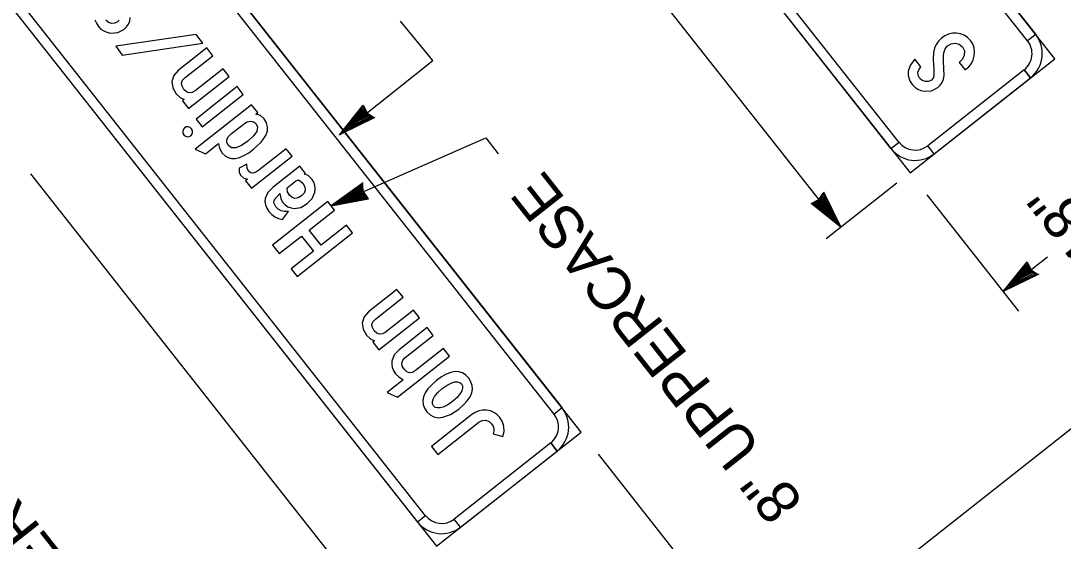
# Model space of a CAD drawing. Extents: x 672438 to 673980, y 1673259 to 1674850.
# Drawn here: x 673725.7 to 673827.5, y 1673361.1 to 1673411.9 of the extents above; entities that cross this region are included whole.
import ezdxf

# ---------------------------------------------------------------- set-up
doc = ezdxf.new("R2010")
doc.units = 0
doc.layers.add('C-ANNO-SYMB', color=7, linetype='Continuous')
doc.layers.add('Level 1', color=7, linetype='Continuous')

msp = doc.modelspace()

# ---------------------------------------------------------------- linework, layer by layer
at = {"layer": 'C-ANNO-SYMB'}
for p, q in [((673826.68, 1673408.21), (673748.67, 1673507.16)), ((673750.53, 1673504.8), (673824.82, 1673410.57)), ((673824.03, 1673409.95), (673749.74, 1673504.19)), ((673734.53, 1673496.02), (673812.54, 1673397.07)), ((673736.39, 1673493.66), (673810.68, 1673399.42)), ((673811.47, 1673400.04), (673737.18, 1673494.28)), ((673780.41, 1673371.74), (673702.41, 1673470.69)), ((673704.26, 1673468.33), (673778.56, 1673374.1)), ((673777.77, 1673373.48), (673703.48, 1673467.71)), ((673688.27, 1673459.54), (673766.28, 1673360.6)), ((673765.2, 1673363.57), (673690.91, 1673457.81)), ((673690.13, 1673457.19), (673764.42, 1673362.95)), ((673824.82, 1673410.57), (673824.03, 1673409.95)), ((673824.82, 1673410.57), (673824.03, 1673409.95)), ((673824.03, 1673409.95), (673824.03, 1673409.95)), ((673824.03, 1673409.95), (673824.03, 1673409.95)), ((673812.54, 1673397.07), (673826.68, 1673408.21)), ((673826.68, 1673408.21), (673826.68, 1673408.21)), ((673826.68, 1673408.21), (673826.68, 1673408.21)), ((673823.7, 1673407.14), (673814.28, 1673399.71)), ((673823.7, 1673407.14), (673824.32, 1673406.35)), ((673824.32, 1673406.35), (673823.7, 1673407.14)), ((673823.7, 1673407.14), (673824.32, 1673406.35)), ((673814.9, 1673398.92), (673824.32, 1673406.35)), ((673811.47, 1673400.04), (673810.68, 1673399.42)), ((673811.47, 1673400.04), (673810.68, 1673399.42)), ((673814.9, 1673398.92), (673814.28, 1673399.71)), ((673814.28, 1673399.71), (673814.28, 1673399.71)), ((673814.28, 1673399.71), (673814.28, 1673399.71)), ((673814.9, 1673398.92), (673814.28, 1673399.71)), ((673778.56, 1673374.1), (673777.77, 1673373.48)), ((673778.56, 1673374.1), (673777.77, 1673373.48)), ((673777.77, 1673373.48), (673777.77, 1673373.48)), ((673777.77, 1673373.48), (673777.77, 1673373.48)), ((673766.28, 1673360.6), (673780.41, 1673371.74)), ((673780.41, 1673371.74), (673780.41, 1673371.74)), ((673780.41, 1673371.74), (673780.41, 1673371.74)), ((673777.44, 1673370.67), (673768.01, 1673363.24)), ((673777.44, 1673370.67), (673778.06, 1673369.88)), ((673778.06, 1673369.88), (673777.44, 1673370.67)), ((673777.44, 1673370.67), (673778.06, 1673369.88)), ((673768.63, 1673362.45), (673778.06, 1673369.88)), ((673765.2, 1673363.57), (673764.42, 1673362.95)), ((673765.2, 1673363.57), (673764.42, 1673362.95)), ((673768.63, 1673362.45), (673768.01, 1673363.24)), ((673768.01, 1673363.24), (673768.01, 1673363.24)), ((673768.01, 1673363.24), (673768.01, 1673363.24)), ((673768.63, 1673362.45), (673768.01, 1673363.24))]:
    msp.add_line(p, q, dxfattribs=at)
for points in [[(673732.91, 1673412), (673733.05, 1673411.68), (673733.26, 1673411.36), (673733.5, 1673411.11), (673733.78, 1673410.92), (673734.09, 1673410.79), (673734.44, 1673410.72), (673735.14, 1673410.77), (673735.74, 1673411.08), (673735.99, 1673411.32), (673736.18, 1673411.59), (673736.31, 1673411.9), (673736.37, 1673412.25)], [(673735.29, 1673411.99), (673735.13, 1673411.81), (673734.85, 1673411.67), (673734.53, 1673411.66), (673734.23, 1673411.76), (673733.99, 1673411.97)], [(673748.82, 1673402.94), (673748.21, 1673403.71), (673742.71, 1673399.37), (673743.73, 1673398.93), (673744.98, 1673399.92), (673745.07, 1673399.46), (673745.35, 1673398.99), (673745.62, 1673398.72), (673745.92, 1673398.55), (673746.25, 1673398.46), (673746.62, 1673398.47), (673747.03, 1673398.56), (673747.47, 1673398.75), (673747.94, 1673399.03), (673748.45, 1673399.4), (673749.15, 1673400.05), (673749.6, 1673400.71), (673749.76, 1673401.15), (673749.78, 1673401.57), (673749.68, 1673401.96), (673749.45, 1673402.34), (673749.08, 1673402.65), (673748.63, 1673402.79), (673748.82, 1673402.94)], [(673747.52, 1673401.89), (673747.8, 1673402.05), (673748.1, 1673402.11), (673748.42, 1673402.05), (673748.66, 1673401.85), (673748.81, 1673401.51), (673748.72, 1673401.11), (673748.4, 1673400.67), (673747.85, 1673400.17), (673747.22, 1673399.74), (673746.69, 1673399.51), (673746.27, 1673399.51), (673745.96, 1673399.72), (673745.81, 1673400.01), (673745.81, 1673400.31), (673745.96, 1673400.6), (673746.27, 1673400.9), (673747.52, 1673401.89)], [(673753.49, 1673397.01), (673752.93, 1673397.72), (673750.31, 1673395.65), (673749.8, 1673395.13), (673749.54, 1673394.57), (673749.51, 1673394.25), (673749.56, 1673393.93), (673749.69, 1673393.61), (673749.9, 1673393.3), (673750.18, 1673393), (673750.49, 1673392.77), (673750.85, 1673392.61), (673751.23, 1673392.51), (673751.81, 1673393.28), (673751.43, 1673393.28), (673751.1, 1673393.36), (673750.81, 1673393.52), (673750.58, 1673393.74), (673750.39, 1673394.13), (673750.44, 1673394.46), (673750.98, 1673395.03), (673751.06, 1673394.56), (673751.25, 1673394.19), (673751.5, 1673393.93), (673751.77, 1673393.75), (673752.07, 1673393.63), (673752.39, 1673393.58), (673753.03, 1673393.69), (673753.64, 1673394.05), (673754.12, 1673394.56), (673754.38, 1673395.17), (673754.43, 1673395.52), (673754.4, 1673395.84), (673754.3, 1673396.14), (673754.12, 1673396.42), (673753.74, 1673396.79), (673753.38, 1673396.92), (673753.49, 1673397.01)], [(673751.69, 1673395.59), (673752.52, 1673396.25), (673752.69, 1673396.33), (673752.86, 1673396.33), (673753.04, 1673396.23), (673753.22, 1673396.04), (673753.41, 1673395.71), (673753.44, 1673395.38), (673753.34, 1673395.08), (673753.09, 1673394.81), (673752.76, 1673394.61), (673752.45, 1673394.55), (673752.17, 1673394.64), (673751.91, 1673394.88), (673751.74, 1673395.2), (673751.69, 1673395.59)], [(673766.27, 1673376.76), (673765.81, 1673376.36), (673765.44, 1673375.96), (673765.18, 1673375.57), (673765.01, 1673375.19), (673764.94, 1673374.81), (673764.97, 1673374.44), (673765.1, 1673374.08), (673765.33, 1673373.72), (673765.65, 1673373.41), (673766.02, 1673373.21), (673766.43, 1673373.14), (673766.89, 1673373.18), (673767.65, 1673373.46), (673768.45, 1673373.99), (673768.92, 1673374.39), (673769.29, 1673374.79), (673769.56, 1673375.18), (673769.73, 1673375.56), (673769.81, 1673375.93), (673769.78, 1673376.3), (673769.65, 1673376.66), (673769.43, 1673377.01), (673769.14, 1673377.3), (673768.82, 1673377.51), (673768.47, 1673377.62), (673768.09, 1673377.64), (673767.68, 1673377.56), (673767.24, 1673377.39), (673766.77, 1673377.12), (673766.27, 1673376.76)], [(673766.84, 1673375.98), (673767.32, 1673376.32), (673767.77, 1673376.55), (673768.07, 1673376.64), (673768.33, 1673376.65), (673768.55, 1673376.58), (673768.71, 1673376.44), (673768.81, 1673376.24), (673768.83, 1673376.02), (673768.76, 1673375.77), (673768.6, 1673375.5), (673768.29, 1673375.11), (673767.85, 1673374.73), (673767.38, 1673374.4), (673766.93, 1673374.18), (673766.63, 1673374.1), (673766.38, 1673374.09), (673766.16, 1673374.15), (673766, 1673374.3), (673765.9, 1673374.49), (673765.88, 1673374.71), (673765.95, 1673374.95), (673766.1, 1673375.22), (673766.41, 1673375.6), (673766.84, 1673375.98)]]:
    msp.add_lwpolyline(points, dxfattribs=at)
for points in [[(673743.46, 1673409.73), (673742.8, 1673410.57), (673734.94, 1673409.45), (673735.56, 1673408.57)], [(673817.92, 1673407.11), (673817.97, 1673407.15), (673818.28, 1673407.43), (673818.53, 1673407.74), (673818.7, 1673408.1), (673818.81, 1673408.48), (673818.85, 1673408.89), (673818.8, 1673409.28), (673818.67, 1673409.65), (673818.45, 1673409.99), (673818.16, 1673410.29), (673817.84, 1673410.51), (673817.48, 1673410.65), (673817.08, 1673410.71), (673816.69, 1673410.69), (673816.31, 1673410.6), (673815.95, 1673410.44), (673815.6, 1673410.21), (673815.32, 1673409.93), (673815.09, 1673409.61), (673814.93, 1673409.24), (673814.83, 1673408.82), (673814.8, 1673408.13), (673814.86, 1673407.17), (673814.88, 1673406.51), (673814.79, 1673406.3), (673814.64, 1673406.13), (673814.36, 1673405.98), (673814.04, 1673405.97), (673813.74, 1673406.07), (673813.49, 1673406.28), (673813.33, 1673406.59), (673813.3, 1673406.88), (673813.4, 1673407.13), (673813.61, 1673407.43), (673813.02, 1673408.17), (673812.57, 1673407.62), (673812.36, 1673406.99), (673812.35, 1673406.65), (673812.42, 1673406.32), (673812.56, 1673405.99), (673812.77, 1673405.67), (673813.01, 1673405.42), (673813.29, 1673405.23), (673813.6, 1673405.1), (673813.95, 1673405.03), (673814.64, 1673405.08), (673815.25, 1673405.39), (673815.5, 1673405.63), (673815.69, 1673405.9), (673815.82, 1673406.21), (673815.88, 1673406.56), (673815.82, 1673407.93), (673815.81, 1673408.45), (673815.83, 1673408.8), (673815.96, 1673409.19), (673816.2, 1673409.47), (673816.56, 1673409.67), (673816.95, 1673409.73), (673817.35, 1673409.63), (673817.66, 1673409.38), (673817.85, 1673408.99), (673817.83, 1673408.56), (673817.66, 1673408.17), (673817.34, 1673407.85)], [(673746.02, 1673406.48), (673745.43, 1673407.22), (673742.69, 1673405.06), (673742.42, 1673404.91), (673742.13, 1673404.89), (673741.85, 1673404.98), (673741.61, 1673405.2), (673741.43, 1673405.52), (673741.38, 1673405.82), (673741.48, 1673406.1), (673741.73, 1673406.36), (673744.43, 1673408.49), (673743.83, 1673409.26), (673741.04, 1673407.06), (673740.61, 1673406.57), (673740.44, 1673405.98), (673740.53, 1673405.36), (673740.86, 1673404.77), (673741.23, 1673404.41), (673741.63, 1673404.24), (673741.46, 1673404.11), (673742.05, 1673403.36)], [(673747.4, 1673404.73), (673746.8, 1673405.49), (673742.79, 1673402.32), (673743.39, 1673401.56)], [(673742.29, 1673400.69), (673742.4, 1673400.83), (673742.45, 1673401.01), (673742.43, 1673401.19), (673742.34, 1673401.36), (673742.2, 1673401.5), (673742.02, 1673401.56), (673741.84, 1673401.56), (673741.67, 1673401.47), (673741.55, 1673401.32), (673741.49, 1673401.14), (673741.51, 1673400.95), (673741.6, 1673400.78), (673741.75, 1673400.65), (673741.93, 1673400.59), (673742.12, 1673400.6)], [(673752.17, 1673398.68), (673751.59, 1673399.42), (673748.94, 1673397.32), (673748.63, 1673397.12), (673748.35, 1673397.03), (673748.12, 1673397.07), (673747.93, 1673397.23), (673747.79, 1673397.52), (673747.76, 1673397.92), (673746.99, 1673397.51), (673747.01, 1673397.1), (673747.15, 1673396.79), (673747.45, 1673396.54), (673747.82, 1673396.44), (673747.62, 1673396.29), (673748.2, 1673395.55)], [(673758.07, 1673391.2), (673757.48, 1673391.94), (673755.01, 1673389.99), (673753.84, 1673391.47), (673756.32, 1673393.42), (673755.67, 1673394.25), (673750.27, 1673390), (673750.92, 1673389.17), (673753.09, 1673390.88), (673754.25, 1673389.4), (673752.09, 1673387.69), (673752.67, 1673386.95)], [(673764.61, 1673382.9), (673764.03, 1673383.64), (673761.28, 1673381.48), (673761.01, 1673381.33), (673760.72, 1673381.3), (673760.44, 1673381.4), (673760.2, 1673381.62), (673760.02, 1673381.94), (673759.97, 1673382.24), (673760.07, 1673382.52), (673760.32, 1673382.78), (673763.03, 1673384.91), (673762.42, 1673385.67), (673759.63, 1673383.47), (673759.2, 1673382.98), (673759.03, 1673382.4), (673759.12, 1673381.78), (673759.45, 1673381.19), (673759.82, 1673380.83), (673760.22, 1673380.66), (673760.05, 1673380.52), (673760.64, 1673379.77)], [(673762.62, 1673379.77), (673762.16, 1673379.27), (673761.93, 1673378.68), (673761.92, 1673378.36), (673761.96, 1673378.04), (673762.09, 1673377.74), (673762.28, 1673377.44), (673762.59, 1673377.13), (673763.03, 1673376.84), (673761.45, 1673375.6), (673762.47, 1673375.16), (673767.56, 1673379.16), (673766.97, 1673379.9), (673764.23, 1673377.74), (673763.93, 1673377.56), (673763.64, 1673377.53), (673763.37, 1673377.63), (673763.11, 1673377.87), (673762.93, 1673378.18), (673762.89, 1673378.48), (673762.99, 1673378.75), (673763.23, 1673379.01), (673765.97, 1673381.17), (673765.37, 1673381.94)], [(673772.76, 1673371.32), (673772.88, 1673371.79), (673772.86, 1673372.28), (673772.72, 1673372.74), (673772.46, 1673373.16), (673772.19, 1673373.45), (673771.88, 1673373.66), (673771.54, 1673373.8), (673771.16, 1673373.87), (673770.78, 1673373.87), (673770.41, 1673373.8), (673770.07, 1673373.65), (673769.74, 1673373.44), (673765.79, 1673370.32), (673766.4, 1673369.54), (673770.43, 1673372.71), (673770.74, 1673372.87), (673771.08, 1673372.89), (673771.41, 1673372.77), (673771.67, 1673372.55), (673771.82, 1673372.32), (673771.89, 1673372.07), (673771.89, 1673371.82), (673771.83, 1673371.55)]]:
    msp.add_lwpolyline(points, close=True, dxfattribs=at)
for centre, radius, start, end in [((673822.46, 1673408.71), 2, 308.2504, 38.2506), ((673822.46, 1673408.71), 3, 308.2504, 38.2506), ((673813.04, 1673401.28), 2, 218.2508, 308.2504), ((673813.04, 1673401.28), 3, 218.2508, 308.2504), ((673776.2, 1673372.24), 2, 308.2504, 38.2506), ((673776.2, 1673372.24), 3, 308.2504, 38.2506), ((673766.78, 1673364.81), 2, 218.2508, 308.2504), ((673766.78, 1673364.81), 3, 218.2508, 308.2504)]:
    msp.add_arc(centre, radius, start, end, dxfattribs=at)
at = {"layer": 'Level 1'}
for p, q in [((673979.67, 1673491.41), (673684.88, 1673259.01)), ((673805.78, 1673391.74), (673772.9, 1673433.45)), ((673756.8, 1673400.77), (673759.12, 1673403.68)), ((673757.02, 1673401), (673759.1, 1673403.53)), ((673757.37, 1673401.28), (673759.1, 1673403.36)), ((673757.59, 1673401.38), (673759.14, 1673403.09)), ((673757.66, 1673401.5), (673759.1, 1673403.23)), ((673758.09, 1673401.84), (673759.08, 1673402.95)), ((673758.48, 1673402.11), (673759.05, 1673402.82)), ((673759.14, 1673402.96), (673758.64, 1673402.2)), ((673758.81, 1673402.41), (673759.08, 1673402.74)), ((673759.05, 1673402.82), (673759.33, 1673402.68)), ((673759.08, 1673402.95), (673759.44, 1673402.63)), ((673759.08, 1673402.74), (673759.16, 1673402.68)), ((673759.1, 1673403.53), (673759.44, 1673402.96)), ((673759.1, 1673403.36), (673759.23, 1673403.1)), ((673759.1, 1673403.23), (673759.78, 1673402.53)), ((673759.12, 1673403.68), (673759.51, 1673402.92)), ((673759.14, 1673403.09), (673759.6, 1673402.59)), ((673759.52, 1673402.69), (673759.14, 1673402.96)), ((673759.16, 1673402.68), (673759.52, 1673402.69)), ((673759.23, 1673403.1), (673759.78, 1673402.53)), ((673759.44, 1673402.96), (673760.11, 1673402.49)), ((673759.51, 1673402.92), (673759.75, 1673402.61)), ((673760.26, 1673402.47), (673756.8, 1673400.77)), ((673759.9, 1673402.46), (673757.06, 1673401.03)), ((673760.07, 1673402.42), (673757.22, 1673401.13)), ((673759.78, 1673402.53), (673757.59, 1673401.38)), ((673759.78, 1673402.53), (673757.66, 1673401.5)), ((673759.6, 1673402.59), (673758.09, 1673401.84)), ((673758.64, 1673402.2), (673758.38, 1673402.1)), ((673759.44, 1673402.63), (673758.48, 1673402.11)), ((673759.33, 1673402.68), (673758.81, 1673402.41)), ((673759.75, 1673402.61), (673760.07, 1673402.42)), ((673760.11, 1673402.49), (673759.89, 1673402.55)), ((673759.89, 1673402.55), (673759.9, 1673402.46)), ((673759.52, 1673355.27), (673726.64, 1673396.98)), ((673759.11, 1673396.1), (673755.99, 1673393.83)), ((673758.93, 1673395.79), (673756.35, 1673393.94)), ((673758.97, 1673395.96), (673756.5, 1673394.04)), ((673758.94, 1673395.65), (673756.9, 1673394.25)), ((673758.94, 1673395.65), (673757.04, 1673394.25)), ((673759.01, 1673395.74), (673758.93, 1673395.79)), ((673759.19, 1673394.91), (673758.94, 1673395.65)), ((673759.24, 1673394.73), (673758.94, 1673395.65)), ((673758.99, 1673395.59), (673758.97, 1673395.96)), ((673759.16, 1673395.23), (673758.99, 1673395.59)), ((673759.06, 1673395.97), (673759.01, 1673395.74)), ((673759.16, 1673395.15), (673759.06, 1673395.97)), ((673811.24, 1673396.05), (673804.34, 1673390.6)), ((673756.3, 1673393.92), (673759.51, 1673394.59)), ((673756.47, 1673394.11), (673757.22, 1673394.62)), ((673756.71, 1673394.1), (673759.36, 1673394.66)), ((673757.22, 1673394.62), (673756.71, 1673394.1)), ((673756.9, 1673394.25), (673759.14, 1673394.82)), ((673757.04, 1673394.25), (673759.24, 1673394.73)), ((673757.44, 1673394.46), (673757.82, 1673394.75)), ((673757.91, 1673394.62), (673757.44, 1673394.46)), ((673758.91, 1673395.47), (673757.54, 1673394.48)), ((673757.54, 1673394.48), (673758.99, 1673394.84)), ((673758.12, 1673394.79), (673757.91, 1673394.62)), ((673758.87, 1673395.31), (673757.96, 1673394.7)), ((673757.96, 1673394.7), (673758.86, 1673394.87)), ((673759.03, 1673394.89), (673758.12, 1673394.79)), ((673758.86, 1673395.19), (673758.38, 1673394.86)), ((673758.38, 1673394.86), (673758.8, 1673394.93)), ((673758.78, 1673395.04), (673758.96, 1673395.35)), ((673758.8, 1673394.93), (673758.78, 1673395.04)), ((673758.86, 1673394.87), (673758.86, 1673395.19)), ((673758.99, 1673394.84), (673758.87, 1673395.31)), ((673759.14, 1673394.82), (673758.91, 1673395.47)), ((673758.96, 1673395.35), (673759.03, 1673394.89)), ((673759.65, 1673394.53), (673759.16, 1673395.23)), ((673759.51, 1673394.59), (673759.16, 1673395.15)), ((673759.36, 1673394.66), (673759.19, 1673394.91)), ((673803.32, 1673394.04), (673804.02, 1673394.72)), ((673803.45, 1673394.18), (673804.02, 1673394.72)), ((673803.46, 1673394.08), (673803.96, 1673394.54)), ((673803.59, 1673394.38), (673804.06, 1673395.06)), ((673803.63, 1673394.45), (673803.94, 1673394.7)), ((673803.94, 1673394.7), (673804.13, 1673395.01)), ((673803.96, 1673394.54), (673804.71, 1673393.03)), ((673804.06, 1673395.06), (673804, 1673394.84)), ((673804, 1673394.84), (673804.09, 1673394.84)), ((673804.02, 1673394.72), (673805.05, 1673392.6)), ((673804.02, 1673394.72), (673805.17, 1673392.53)), ((673804.08, 1673395.2), (673805.78, 1673391.74)), ((673804.09, 1673394.84), (673805.52, 1673392)), ((673804.13, 1673395.01), (673805.42, 1673392.16)), ((673814.19, 1673394.92), (673823.14, 1673383.56)), ((673755.99, 1673393.83), (673759.65, 1673394.53)), ((673756.5, 1673394.04), (673756.3, 1673393.92)), ((673756.35, 1673393.94), (673756.47, 1673394.11)), ((673802.87, 1673394.06), (673803.63, 1673394.45)), ((673805.78, 1673391.74), (673802.87, 1673394.06)), ((673803.02, 1673394.04), (673803.59, 1673394.38)), ((673805.55, 1673391.96), (673803.02, 1673394.04)), ((673803.19, 1673394.04), (673803.45, 1673394.18)), ((673805.27, 1673392.31), (673803.19, 1673394.04)), ((673805.05, 1673392.6), (673803.32, 1673394.04)), ((673805.17, 1673392.53), (673803.46, 1673394.08)), ((673803.86, 1673394.46), (673803.59, 1673394.09)), ((673803.59, 1673394.09), (673804.35, 1673393.58)), ((673803.6, 1673394.03), (673803.92, 1673394.38)), ((673804.71, 1673393.03), (673803.6, 1673394.03)), ((673803.73, 1673393.99), (673803.87, 1673394.27)), ((673804.44, 1673393.42), (673803.73, 1673393.99)), ((673803.81, 1673394.02), (673803.87, 1673394.11)), ((673804.14, 1673393.76), (673803.81, 1673394.02)), ((673803.87, 1673394.11), (673803.86, 1673394.46)), ((673803.87, 1673394.27), (673804.14, 1673393.76)), ((673803.92, 1673394.38), (673804.44, 1673393.42)), ((673804.35, 1673393.58), (673804.45, 1673393.33)), ((673804.45, 1673393.33), (673804.8, 1673392.97)), ((673804.8, 1673392.97), (673804.59, 1673393.4)), ((673805.49, 1673392.21), (673805.06, 1673393.01)), ((673805.06, 1673393.01), (673805.27, 1673392.31)), ((673805.42, 1673392.16), (673805.55, 1673391.96)), ((673805.52, 1673392), (673805.49, 1673392.21)), ((673821.65, 1673385.46), (673825.97, 1673388.86)), ((673821.65, 1673385.46), (673823.97, 1673388.36)), ((673821.87, 1673385.69), (673823.95, 1673388.22)), ((673822.22, 1673385.97), (673823.95, 1673388.05)), ((673822.44, 1673386.07), (673823.99, 1673387.78)), ((673822.51, 1673386.19), (673823.95, 1673387.92)), ((673822.94, 1673386.53), (673823.94, 1673387.64)), ((673823.33, 1673386.8), (673823.9, 1673387.51)), ((673823.99, 1673387.65), (673823.49, 1673386.89)), ((673823.66, 1673387.09), (673823.93, 1673387.43)), ((673823.9, 1673387.51), (673824.18, 1673387.36)), ((673823.93, 1673387.43), (673824.01, 1673387.37)), ((673823.94, 1673387.64), (673824.29, 1673387.32)), ((673823.95, 1673388.22), (673824.29, 1673387.65)), ((673823.95, 1673388.05), (673824.09, 1673387.79)), ((673823.95, 1673387.92), (673824.63, 1673387.22)), ((673823.97, 1673388.36), (673824.36, 1673387.6)), ((673823.99, 1673387.78), (673824.45, 1673387.28)), ((673824.37, 1673387.38), (673823.99, 1673387.65)), ((673824.09, 1673387.79), (673824.63, 1673387.22)), ((673824.29, 1673387.65), (673824.96, 1673387.18)), ((673824.36, 1673387.6), (673824.6, 1673387.29)), ((673825.11, 1673387.16), (673821.65, 1673385.46)), ((673824.75, 1673387.14), (673821.91, 1673385.72)), ((673824.92, 1673387.11), (673822.07, 1673385.81)), ((673824.63, 1673387.22), (673822.44, 1673386.07)), ((673824.63, 1673387.22), (673822.51, 1673386.19)), ((673823.23, 1673386.79), (673822.87, 1673386.44)), ((673822.87, 1673386.44), (673823.31, 1673386.65)), ((673824.45, 1673387.28), (673822.94, 1673386.53)), ((673823.49, 1673386.89), (673823.23, 1673386.79)), ((673824.29, 1673387.32), (673823.33, 1673386.8)), ((673824.18, 1673387.36), (673823.66, 1673387.09)), ((673824.01, 1673387.37), (673824.37, 1673387.38)), ((673824.6, 1673387.29), (673824.92, 1673387.11)), ((673824.96, 1673387.18), (673824.74, 1673387.24)), ((673824.74, 1673387.24), (673824.75, 1673387.14)), ((673822.07, 1673385.81), (673821.87, 1673385.69)), ((673821.91, 1673385.72), (673822.12, 1673385.75)), ((673822.12, 1673385.75), (673822.91, 1673386.18)), ((673822.91, 1673386.18), (673822.22, 1673385.97)), ((673782.06, 1673369.59), (673790.89, 1673358.39))]:
    msp.add_line(p, q, dxfattribs=at)
for points in [[(673756.8, 1673400.77), (673765.91, 1673408.03), (673762.77, 1673411.88)], [(673755.99, 1673393.83), (673771.1, 1673400.47), (673772.32, 1673398.92)]]:
    msp.add_lwpolyline(points, dxfattribs=at)

# ---------------------------------------------------------------- texts
for s, p in [('8" UPPERCASE', (673848.67, 1673401.23)), ('8" UPPERCASE', (673802.24, 1673364.97)), ('18"', (673832.19, 1673390.29)), ('8" UPPERCASE', (673741.35, 1673345.1))]:
    msp.add_text(s, height=4.2, rotation=128.2505, dxfattribs=at).set_placement(p)

doc.saveas('drawing.dxf')
